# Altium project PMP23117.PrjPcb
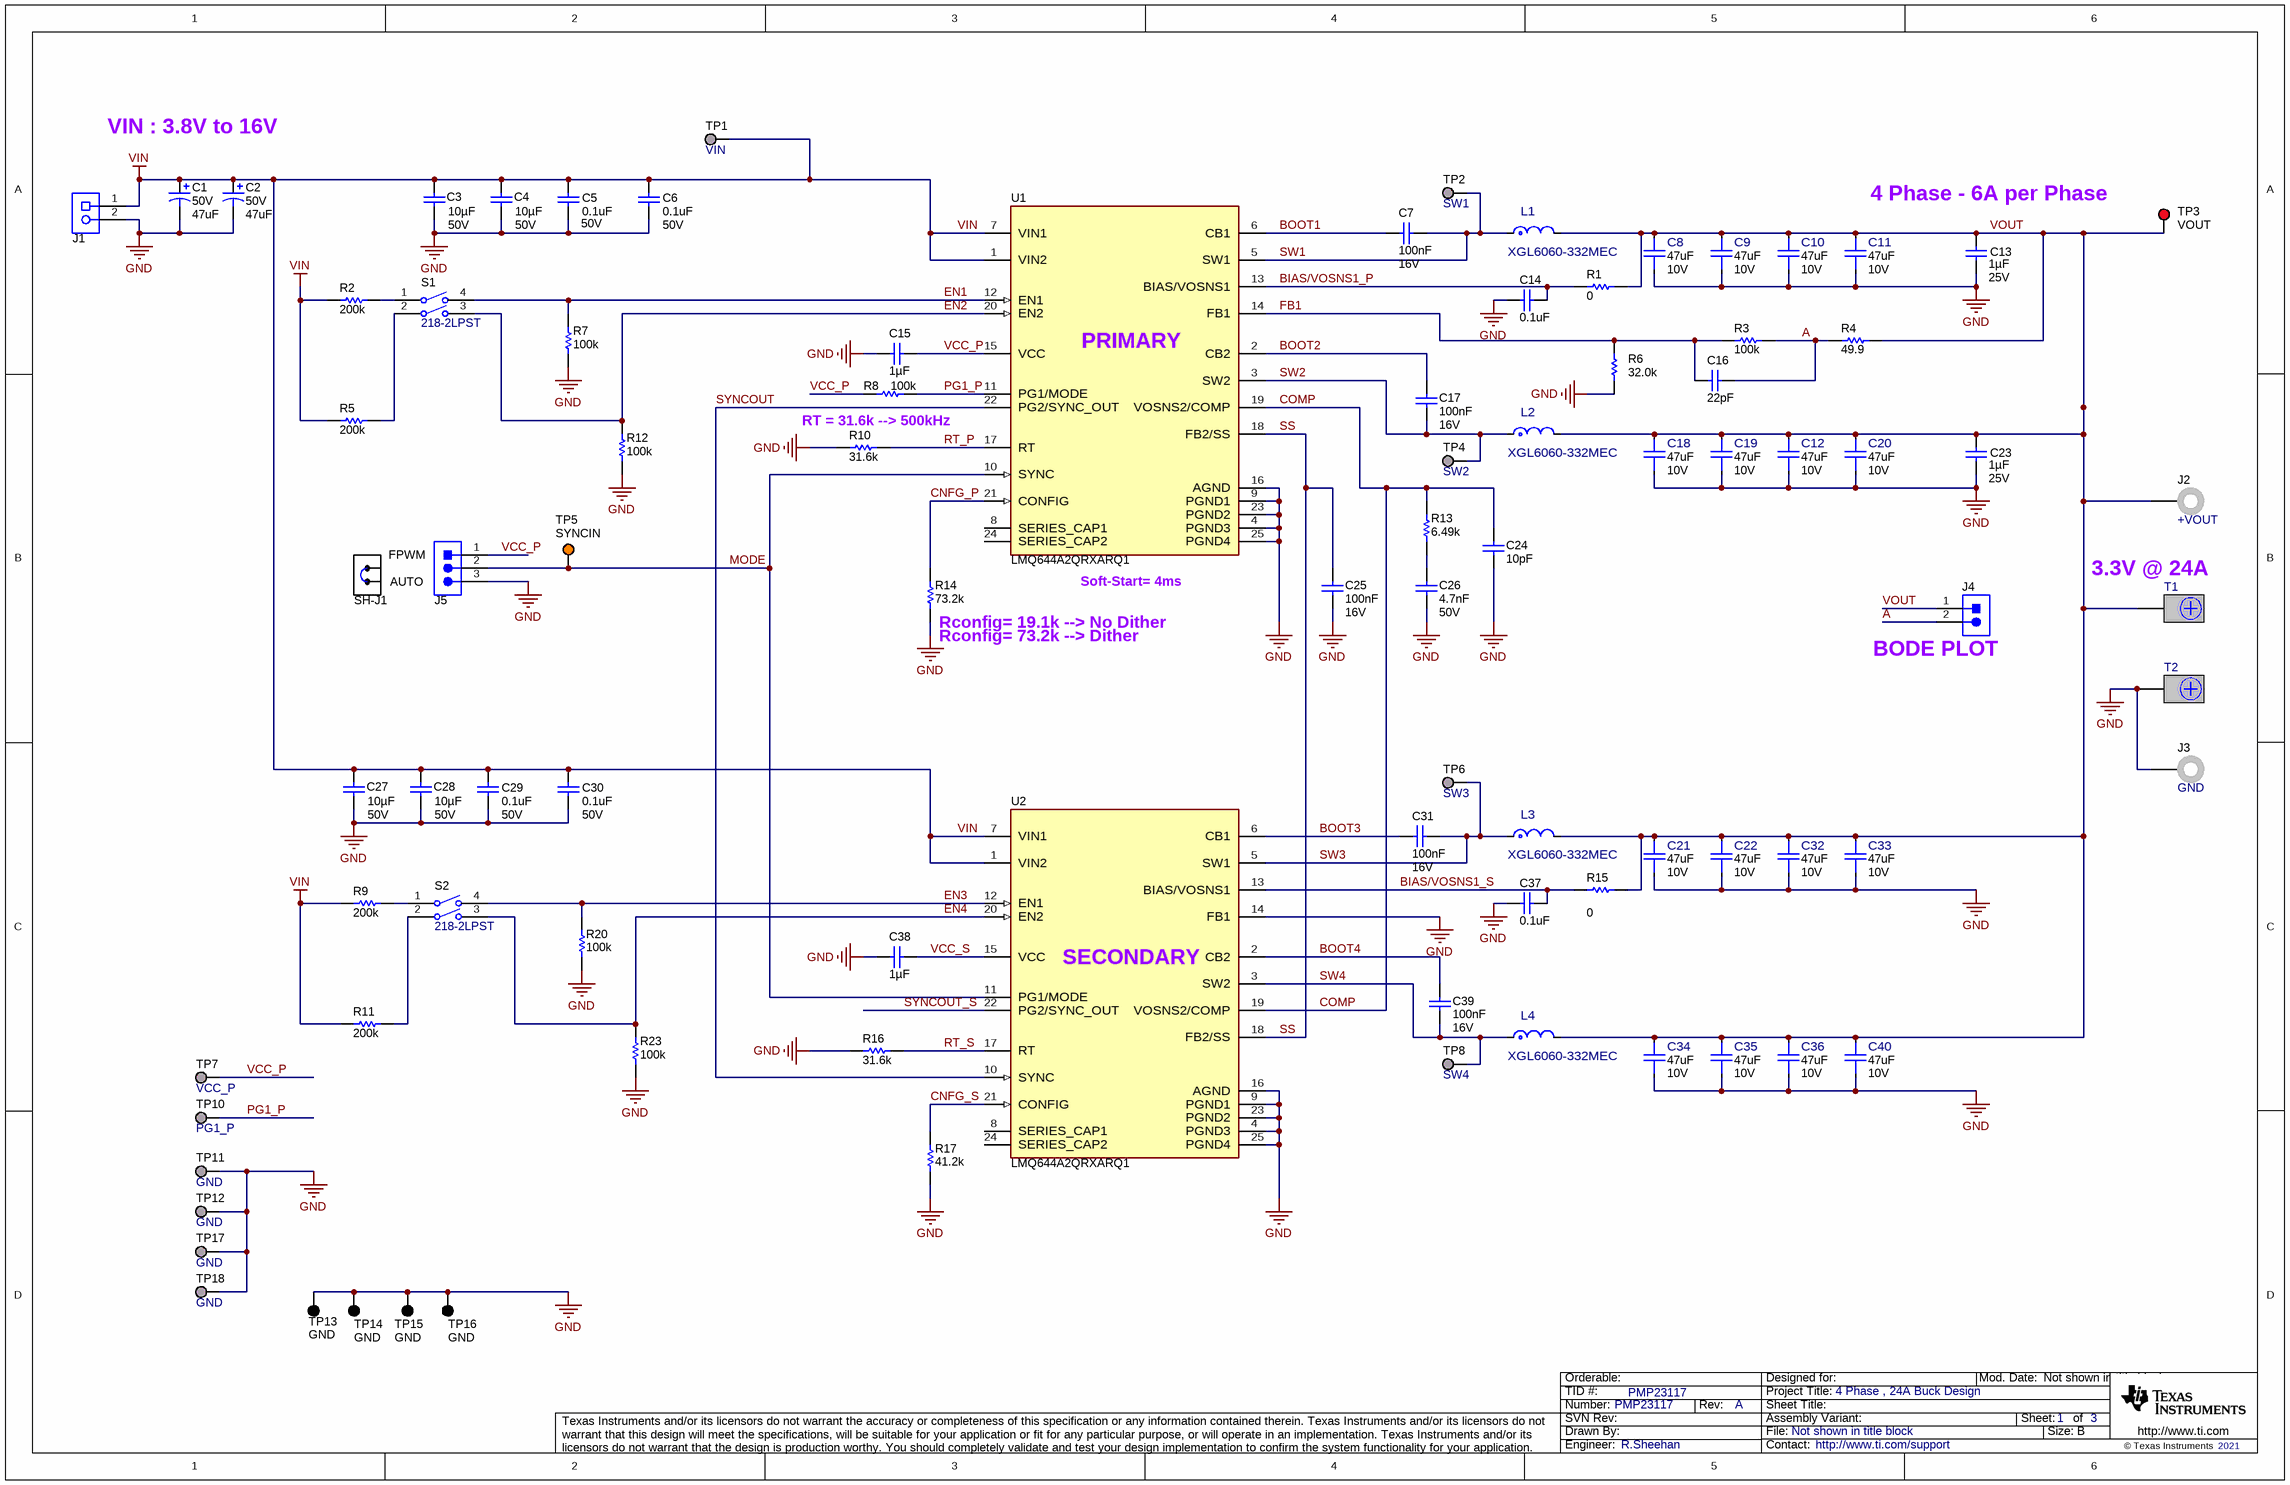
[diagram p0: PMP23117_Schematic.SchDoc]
CopyrightYear: 2021; PCB_Layout: R.Sheehan; PCB_Rev: A; PRJ_Engineer: R.Sheehan; PRJ_Number: PMP23117; PRJ_Title: 4 Phase , 24A Buck Design; SCH_Rev: A; TechSupport: http://www.ti.com/support; TID: PMP23117
3 sheets, 127 parts. Net scope: global (net labels, ports and power ports of the same name join across sheets).
Board file: PMP23117.PcbDoc
Sheets:
  PMP23117_Schematic.SchDoc
  PMP23117_EMI_Filter.SchDoc
  PMP23117_Hardware.SchDoc

## Sheet PMP23117_Schematic.SchDoc
size 431 x 279 mm; Date: Not shown in title block; ApprovedBy: Not shown in title block; CheckedBy: Not shown in title block; Author: Not shown in title block; CompanyName: Not shown in title block; Engineer: Not shown in title block; Organization: Not shown in title block; Address1: Not shown in title block; Address2: Not shown in title block; Address3: Not shown in title block; Address4: Not shown in title block; DocumentNumber: 1; Revision: Use project parameter SCH_Rev; SheetNumber: 1; SheetTotal: 3; PageSetup: Record=PageOptions¦CenterHorizontal=True¦CenterVertical=True¦PrintScale=1.00¦XCorrection=1.00¦YCorrection=1.00¦PrintKind=0¦BorderSize=5000000¦LeftOffset=0¦BottomOffset=0¦Orientation=2¦PaperLength=1000¦PaperWidth=1000¦Scale=100¦PaperSource=15¦PrintQuality=600¦MediaType=1¦DitherType=10¦PaperKind=Letter¦PrintScaleMode=1

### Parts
C1  VDC_V: 50V  ValueDisplayed: 47uF  [Panasonic_D]  (hidden comment: Cinblk)
C2  VDC_V: 50V  ValueDisplayed: 47uF  [Panasonic_D]  (hidden comment: Cinblk)
C3  ValueDisplayed: 10µF  VDC_V: 50V  [1206_190]  (hidden comment: CIN1_P)
C4  ValueDisplayed: 10µF  VDC_V: 50V  [1206_190]  (hidden comment: CIN2_P)
C5  VDC_V: 50V  ValueDisplayed: 0.1uF  [0402S]  (hidden comment: CHF2_P)
C6  VDC_V: 50V  ValueDisplayed: 0.1uF  [0402S]  (hidden comment: CHF1_P)
C7  Cap_F: 100nF  VDC_V: 16V  [0603L]  (hidden comment: GCM188R71C104KA37J)
C8  ValueDisplayed: 47uF  VDC_V: 10V  [FP-GRT32EC81A476KE13K_1210-MFG]  (hidden comment: GRT32EC81A476KE13K)
C9  ValueDisplayed: 47uF  VDC_V: 10V  [FP-GRT32EC81A476KE13K_1210-MFG]  (hidden comment: GRT32EC81A476KE13K)
C10  ValueDisplayed: 47uF  VDC_V: 10V  [FP-GRT32EC81A476KE13K_1210-MFG]  (hidden comment: GRT32EC81A476KE13K)
C11  ValueDisplayed: 47uF  VDC_V: 10V  [FP-GRT32EC81A476KE13K_1210-MFG]  (hidden comment: GRT32EC81A476KE13K)
C12  ValueDisplayed: 47uF  VDC_V: 10V  [FP-GRT32EC81A476KE13K_1210-MFG]  (hidden comment: GRT32EC81A476KE13K)
C13  Cap_F: 1µF  VDC_V: 25V  [0603L]  (hidden comment: Co11)
C14  ValueDisplayed: 0.1uF  [0603L]  (hidden comment: CBIAS_P)
C15  Cap_F: 1µF  [0603L]  (hidden comment: CVCC_P)
C16  ValueDisplayed: 22pF  [0603L]  (hidden comment: CFF)
C17  Cap_F: 100nF  VDC_V: 16V  [0603L]  (hidden comment: GCM188R71C104KA37J)
C18  ValueDisplayed: 47uF  VDC_V: 10V  [FP-GRT32EC81A476KE13K_1210-MFG]  (hidden comment: GRT32EC81A476KE13K)
C19  ValueDisplayed: 47uF  VDC_V: 10V  [FP-GRT32EC81A476KE13K_1210-MFG]  (hidden comment: GRT32EC81A476KE13K)
C20  ValueDisplayed: 47uF  VDC_V: 10V  [FP-GRT32EC81A476KE13K_1210-MFG]  (hidden comment: GRT32EC81A476KE13K)
C21  ValueDisplayed: 47uF  VDC_V: 10V  [FP-GRT32EC81A476KE13K_1210-MFG]  (hidden comment: GRT32EC81A476KE13K)
C22  ValueDisplayed: 47uF  VDC_V: 10V  [FP-GRT32EC81A476KE13K_1210-MFG]  (hidden comment: GRT32EC81A476KE13K)
C23  Cap_F: 1µF  VDC_V: 25V  [0603L]  (hidden comment: Co12)
C24  ValueDisplayed: 10pF  [0603L]  (hidden comment: CHFP)
C25  Cap_F: 100nF  VDC_V: 16V  [0603L]  (hidden comment: GCM188R71C104KA37J)
C26  Cap_F: 4.7nF  VDC_V: 50V  [0603L]  (hidden comment: GCM188R71H472KA37D)
C27  ValueDisplayed: 10µF  VDC_V: 50V  [1206_190]  (hidden comment: CIN1_S)
C28  ValueDisplayed: 10µF  VDC_V: 50V  [1206_190]  (hidden comment: CIN2_S)
C29  VDC_V: 50V  ValueDisplayed: 0.1uF  [0402S]  (hidden comment: CHF2_S)
C30  VDC_V: 50V  ValueDisplayed: 0.1uF  [0402S]  (hidden comment: CHF1_S)
C31  Cap_F: 100nF  VDC_V: 16V  [0603L]  (hidden comment: GCM188R71C104KA37J)
C32  ValueDisplayed: 47uF  VDC_V: 10V  [FP-GRT32EC81A476KE13K_1210-MFG]  (hidden comment: GRT32EC81A476KE13K)
C33  ValueDisplayed: 47uF  VDC_V: 10V  [FP-GRT32EC81A476KE13K_1210-MFG]  (hidden comment: GRT32EC81A476KE13K)
C34  ValueDisplayed: 47uF  VDC_V: 10V  [FP-GRT32EC81A476KE13K_1210-MFG]  (hidden comment: GRT32EC81A476KE13K)
C35  ValueDisplayed: 47uF  VDC_V: 10V  [FP-GRT32EC81A476KE13K_1210-MFG]  (hidden comment: GRT32EC81A476KE13K)
C36  ValueDisplayed: 47uF  VDC_V: 10V  [FP-GRT32EC81A476KE13K_1210-MFG]  (hidden comment: GRT32EC81A476KE13K)
C37  ValueDisplayed: 0.1uF  [0603L]  (hidden comment: CBIAS_S)
C38  Cap_F: 1µF  [0603L]  (hidden comment: CVCC_S)
C39  Cap_F: 100nF  VDC_V: 16V  [0603L]  (hidden comment: GCM188R71C104KA37J)
C40  ValueDisplayed: 47uF  VDC_V: 10V  [FP-GRT32EC81A476KE13K_1210-MFG]  (hidden comment: GRT32EC81A476KE13K)
J1  VIN  [Wurth_691101710002]  (value not drawn)
J2  +VOUT  [Johnson_108-0740-001]
J3  GND  [Johnson_108-0740-001]
J4  BODE  [TSW-102-07-G-S]  (value not drawn)
J5  MODE  [PBC03SAAN]  (value not drawn)
L1  XGL6060-332MEC  [FP-XGL6060-332MEC_SMT_6MM51_6MM71-MFG]
L2  XGL6060-332MEC  [FP-XGL6060-332MEC_SMT_6MM51_6MM71-MFG]
L3  XGL6060-332MEC  [FP-XGL6060-332MEC_SMT_6MM51_6MM71-MFG]
L4  XGL6060-332MEC  [FP-XGL6060-332MEC_SMT_6MM51_6MM71-MFG]
R1  ValueDisplayed: 0  [0402L]  (hidden comment: RSNS1_P)
R2  ValueDisplayed: 200k  [0603L]  (hidden comment: CRCW0603200KFKEA)
R3  ValueDisplayed: 100k  [0603L]  (hidden comment: RFBT)
R4  ValueDisplayed: 49.9  [0805L]  (hidden comment: RINJ)
R5  ValueDisplayed: 200k  [0603L]  (hidden comment: CRCW0603200KFKEA)
R6  ValueDisplayed: 32.0k  [0603L]  (hidden comment: RFBB)
R7  ValueDisplayed: 100k  [0603L]  (hidden comment: CRCW0603100KFKEA)
R8  ValueDisplayed: 100k  [0603L]  (hidden comment: RPG1_P)
R9  ValueDisplayed: 200k  [0603L]  (hidden comment: CRCW0603200KFKEA)
R10  ValueDisplayed: 31.6k  [0603L]  (hidden comment: CRCW060331K6FKEA)
R11  ValueDisplayed: 200k  [0603L]  (hidden comment: CRCW0603200KFKEA)
R12  ValueDisplayed: 100k  [0603L]  (hidden comment: CRCW0603100KFKEA)
R13  ValueDisplayed: 6.49k  [0603L]  (hidden comment: CRCW06036K49FKEA)
R14  ValueDisplayed: 73.2k  [0603L]  (hidden comment: CRCW060373K2FKEA)
R15  ValueDisplayed: 0  [0402L]  (hidden comment: RSNS1_S)
R16  ValueDisplayed: 31.6k  [0603L]  (hidden comment: CRCW060331K6FKEA)
R17  ValueDisplayed: 41.2k  [0603L]  (hidden comment: CRCW060341K2FKEA)
R20  ValueDisplayed: 100k  [0603L]  (hidden comment: CRCW0603100KFKEA)
R23  ValueDisplayed: 100k  [0603L]  (hidden comment: CRCW0603100KFKEA)
S1  218-2LPST  [SW_218-2LP]
S2  218-2LPST  [SW_218-2LP]
SH-J1  SNT-100-BK-G  [SNT-100-BK-G]  (value not drawn)
T1  VOUT  [Panduit_CXS70-14-C]  (value not drawn)
T2  GND  [Panduit_CXS70-14-C]  (value not drawn)
TP1  VIN  [Harwin_S2751-46R]  (mechanical)
TP2  SW1  [Harwin_S2751-46R]  (mechanical)
TP3  VOUT  [Keystone5010]
TP4  SW2  [Harwin_S2751-46R]  (mechanical)
TP5  SYNCIN  [Keystone5013]
TP6  SW3  [Harwin_S2751-46R]  (mechanical)
TP7  VCC_P  [Harwin_S2751-46R]  (mechanical)
TP8  SW4  [Harwin_S2751-46R]  (mechanical)
TP10  PG1_P  [Harwin_S2751-46R]  (mechanical)
TP11  GND  [Harwin_S2751-46R]  (mechanical)
TP12  GND  [Harwin_S2751-46R]  (mechanical)
TP13  GND  [Keystone5011]
TP14  GND  [Keystone5011]
TP15  GND  [Keystone5011]
TP16  GND  [Keystone5011]
TP17  GND  [Harwin_S2751-46R]  (mechanical)
TP18  GND  [Harwin_S2751-46R]  (mechanical)
U1  LMQ644A2QRXARQ1  [RXA0024A-MFG]
U2  LMQ644A2QRXARQ1  [RXA0024A-MFG]

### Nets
GND: C1.2(-) C2.2(-) C3.1 C4.1 C5.2 C6.2 C8.1 C9.1 C10.1 C11.1 C12.1 C13.2 C14.1 C15.1 C18.1 C19.1 C20.1 C21.1 C22.1 C23.2 C24.1 C25.1 C26.2 C27.1 C28.1 C29.2 C30.2 C32.1 C33.1 C34.1 C35.1 C36.1 C37.1 C38.1 C40.1 J1.2 J3.1 J5.3 R6.1 R7.1 R10.1 R12.1 R14.1 R16.1 R17.1 R20.1 R23.1 T2.1 TP11.1 TP12.1 TP13.1 TP14.1 TP15.1 TP16.1 TP17.1 TP18.1 U1.4(PGND3) U1.9(PGND1) U1.16(AGND) U1.23(PGND2) U1.25(PGND4) U2.4(PGND3) U2.9(PGND1) U2.14(FB1) U2.16(AGND) U2.23(PGND2) U2.25(PGND4)
VIN: C1.1(+) C2.1(+) C3.2 C4.2 C5.1 C6.1 C27.2 C28.2 C29.1 C30.1 J1.1 R2.1 R5.1 R9.1 R11.1 TP1.1 U1.1(VIN2) U1.7(VIN1) U2.1(VIN2) U2.7(VIN1)
A: C16.1 J4.2 R3.1 R4.1
BIAS/VOSNS1_P: C14.2 R1.1 U1.13(BIAS/VOSNS1)
BIAS/VOSNS1_S: C37.2 R15.2 U2.13(BIAS/VOSNS1)
BOOT1: C7.1 U1.6(CB1)
BOOT2: C17.2 U1.2(CB2)
BOOT3: C31.2 U2.6(CB1)
BOOT4: C39.1 U2.2(CB2)
CNFG_P: R14.2 U1.21(CONFIG)
CNFG_S: R17.2 U2.21(CONFIG)
COMP: C24.2 R13.2 U1.19(VOSNS2/COMP) U2.19(VOSNS2/COMP)
EN1: R7.2 S1.4 U1.12(EN1)
EN2: R12.2 S1.3 U1.20(EN2)
EN3: R20.2 S2.4 U2.12(EN1)
EN4: R23.2 S2.3 U2.20(EN2)
FB1: C16.2 R3.2 R6.2 U1.14(FB1)
MODE: J5.2 TP5.1 U1.10(SYNC) U2.11(PG1/MODE)
PG1_P: R8.2 TP10.1 U1.11(PG1/MODE)
RT_P: R10.2 U1.17(RT)
RT_S: R16.2 U2.17(RT)
SS: C25.2 U1.18(FB2/SS) U2.18(FB2/SS)
SW1: C7.2 L1.1 TP2.1 U1.5(SW1)
SW2: C17.1 L2.1 TP4.1 U1.3(SW2)
SW3: C31.1 L3.1 TP6.1 U2.5(SW1)
SW4: C39.2 L4.1 TP8.1 U2.3(SW2)
SYNCOUT: U1.22(PG2/SYNC_OUT) U2.10(SYNC)
SYNCOUT_S: U2.22(PG2/SYNC_OUT)
VCC_P: C15.2 J5.1 R8.1 TP7.1 U1.15(VCC)
VCC_S: C38.2 U2.15(VCC)
VOUT: C8.2 C9.2 C10.2 C11.2 C12.2 C13.1 C18.2 C19.2 C20.2 C21.2 C22.2 C23.1 C32.2 C33.2 C34.2 C35.2 C36.2 C40.2 J2.1 J4.1 L1.2 L2.2 L3.2 L4.2 R1.2 R4.2 R15.1 T1.1 TP3.1
NetC26_1: C26.1 R13.1
NetR2_2: R2.2 S1.1
NetR5_2: R5.2 S1.2
NetR9_2: R9.2 S2.1
NetR11_2: R11.2 S2.2

Not connected (* = marked no-connect by the designer): U1 8(SERIES_CAP1) 24(SERIES_CAP2); U2 8(SERIES_CAP1) 24(SERIES_CAP2)

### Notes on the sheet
- VIN : 3.8V to 16V
- 4 Phase - 6A per Phase
- (near U1) PRIMARY
- RT = 31.6k --> 500kHz
- FPWM
- (near T1) 3.3V @ 24A
- AUTO
- (near R14) Rconfig= 73.2k --> Dither
- (near R14) Rconfig= 19.1k --> No Dither
- (near U1) Soft-Start= 4ms
- (near J4) BODE PLOT
- (near U2) SECONDARY

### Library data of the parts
C1 C2 = CMP-0011204-2: CAP, AL, 47 uF, 50 V, +/- 20%, 0.68 ohm, AEC-Q200 Grade 2, SMD; Manufacturer: Panasonic; PartNumber: EEEFT1H470AP; TaMin_C: -55°C; ESR_ohm: 6.8d; Polarized: Y; SizeAreaWB_mm2: 73.96; U/M: EA; Value: 47uF; TaMax_C: 105°C; SizeZ_mm: 6.1; SizeX_mm: 6.6; Cap_Case: 6.3x5.8mm; SizeArea_mm2: 43.56; CompType: Capacitor; Cap_F: 47µF; IRMS_A: 1.95dA; AEC Grade: 2; AEC Category: Q200
C3 C4 C27 C28 = CMP-0085950-1: CAP, CERM, 10 µF, 50 V,+/- 10%, X7R, AEC-Q200 Grade 1, 1206; Manufacturer: TDK; PartNumber: CGA5L1X7R1H106K160AC; SizeZ_mm: 1.9; Value: 10uF; Cap_Case: 1206; AEC Grade: 1; TaMin_C: -55°C; U/M: EA; CompType: Capacitor; SizeArea_mm2: 5.12; TaMax_C: 125°C; AEC Qualified: Y; AEC Category: Q200; SizeX_mm: 3.2; SizeY_mm: 1.6; Polarized: N; SizeAreaWB_mm2: 10.92
C5 C6 C29 C30 = CMP-0006356-2: CAP, CERM, 0.1 uF, 50 V, +/- 10%, X7R, AEC-Q200 Grade 1, 0402; Manufacturer: MuRata; PartNumber: GCM155R71H104KE02D; TaMin_C: -55°C; Polarized: N; SizeAreaWB_mm2: 3; Value1: Unknown; U/M: EA; Value: 0.1uF; TaMax_C: 125°C; SizeZ_mm: 0.6; SizeX_mm: 1; SizeY_mm: 0.5; Cap_Case: 0402; AEC Qualified: Y; Cap_F: 100nF; AEC Category: Q200
C7 C17 C25 C31 C39 = CMP-0007135-4: CAP, CERM, 0.1 uF, 16 V, +/- 10%, X7R, AEC-Q200 Grade 1, 0603; Manufacturer: MuRata; TaMin_C: -55°C; Polarized: N; SizeAreaWB_mm2: 4.68; Value1: Unknown; U/M: EA; Value: 0.1uF; TaMax_C: 125°C; SizeZ_mm: 1; SizeX_mm: 1.6; SizeY_mm: 0.8; Cap_Case: 0603; SizeArea_mm2: 1.28; AEC Qualified: Y; AEC Category: Q200
C8-C12 C18-C22 C32-C36 C40 = CMP-0093224-1: Multi-Layer Ceramic Capacitor 47uF 10VDC X6S 10% 1210 Emboss T/R; Manufacturer: Murata; SizeZ_mm: 2.7mm; TempCo: 22%; Value: 47µF; AEC Qualified: Yes; AEC Grade: Grade 1
C13 C23 = CMP-0007139-4: CAP, CERM, 1 uF, 25 V, +/- 10%, X7R, AEC-Q200 Grade 1, 0603; Manufacturer: MuRata; PartNumber: GCM188R71E105KA64D; TaMin_C: -55°C; Polarized: N; SizeAreaWB_mm2: 4.68; Value1: Unknown; U/M: EA; Value: 1uF; TaMax_C: 125°C; SizeZ_mm: 1; SizeX_mm: 1.6; SizeY_mm: 0.8; Cap_Case: 0603; SizeArea_mm2: 1.28; CompType: Capacitor; AEC Qualified: Y; AEC Category: Q200
C14 C37 = CMP-0007010-5: CAP, CERM, 0.1 uF, 50 V, +/- 10%, X5R, 0603; Manufacturer: TDK; PartNumber: C1608X5R1H104K080AA; TaMin_C: -55°C; ESR_ohm: 0.0296; Polarized: N; SizeAreaWB_mm2: 4.68; Value1: 0.0296 ohm; U/M: EA; Value: 0.1uF; TaMax_C: 85°C; SizeZ_mm: 1; SizeX_mm: 1.6; SizeY_mm: 0.8; Cap_Case: 0603; Value2: 50V; SizeArea_mm2: 1.28; Cap_F: 100nF; IRMS_A: 971.99mA; AEC Category: Q200
C15 C38 = CMP-0007137-5: CAP, CERM, 1 uF, 16 V, +/- 20%, X7R, AEC-Q200 Grade 1, 0603; Manufacturer: MuRata; PartNumber: GCM188R71C105MA64D; TaMin_C: -55°C; Polarized: N; SizeAreaWB_mm2: 4.68; Value1: Unknown; U/M: EA; Value: 1uF; TaMax_C: 125°C; SizeZ_mm: 1; SizeX_mm: 1.6; SizeY_mm: 0.8; Cap_Case: 0603; Value2: 16V; SizeArea_mm2: 1.28; CompType: Capacitor; AEC Qualified: Y; AEC Category: Q200
C16 = CMP-0006775-4: CAP, CERM, 22 pF, 50 V, +/- 5%, C0G/NP0, 0603; Manufacturer: AVX; PartNumber: 06035A220JAT2A; TaMin_C: -55°C; ESR_ohm: 0.259; Polarized: N; SizeAreaWB_mm2: 4.68; Value1: 0.259 ohm; U/M: EA; Value: 22pF; TaMax_C: 125°C; SizeZ_mm: 1; SizeX_mm: 1.6; SizeY_mm: 0.8; Cap_Case: 0603; Value2: 50V; SizeArea_mm2: 1.28; CompType: Capacitor; AEC Category: Q200
C24 = CMP-0007236-4: CAP, CERM, 10 pF, 100 V, +/- 5%, C0G/NP0, 0603; Manufacturer: MuRata; PartNumber: GRM1885C2A100JA01D; TaMin_C: -55°C; Polarized: N; SizeAreaWB_mm2: 4.68; Value1: Unknown; U/M: EA; Value: 10pF; TaMax_C: 125°C; SizeZ_mm: 1; SizeX_mm: 1.6; SizeY_mm: 0.8; Cap_Case: 0603; Value2: 100V; SizeArea_mm2: 1.28; CompType: Capacitor; AEC Category: Q200
C26 = CMP-0007146-4: CAP, CERM, 4700 pF, 50 V, +/- 10%, X7R, AEC-Q200 Grade 1, 0603; Manufacturer: MuRata; TaMin_C: -55°C; Polarized: N; SizeAreaWB_mm2: 4.68; Value1: Unknown; U/M: EA; Value: 4700pF; TaMax_C: 125°C; SizeZ_mm: 1; SizeX_mm: 1.6; SizeY_mm: 0.8; Cap_Case: 0603; SizeArea_mm2: 1.28; AEC Qualified: Y; AEC Category: Q200
J1 = CMP-0054828-1: Terminal Block, 5 mm, 2x1, Tin, TH; Manufacturer: Wurth Elektronik; PartNumber: 691 101 710 002; CNHeader: FALSE; Green_Lifecycle: Active; Green_REACh: Passed; CT: TRUE
J2 J3 = CMP-0055387-2: Standard Banana Jack, Uninsulated, 15A; Manufacturer: Cinch Connectivity; CNHeader: FALSE; CT: TRUE; Green_Lifecycle: Active; Green_REACh: Passed
J4 = CMP-0075405-3: Header, 100mil, 2x1, Gold, TH; Manufacturer: Samtec; Pitch_mm: 2.54; Cert_VDE: N; Gender: Male; Cert_CSA: Y; Voltage_V: 550V; Green_REACh: Passed; Current_A: 6.3A; Green_Lifecycle: Active; Row_Count: 1
J5 = CMP-0002334-1: Header, 100mil, 3x1, Gold, TH; Manufacturer: Sullins Connector Solutions; CNHeader: TRUE; CT: FALSE; Green_Lifecycle: Not Set; Green_REACh: Incomplete
L1-L4 = CMP-0093175-1: Shielded Power Inductors 3.3uH 20% tol, 6.5mOhm 16.6A; Manufacturer: Coilcraft; Shrouded: true; AEC Grade: Grade 1; TaMin_C: -40°C; Ind_H: 3.3µH; Test Frequency: 1MHz; DCR_ohm: 6.5m; Isat: 6.6A; Material: Composite; Self Resonant Frequency: 24MHz; SizeZ_mm: 6.1mm; AEC Qualified: Yes; TaMax_C: +125°C
R1 R15 = CMP-0081856-1: RES, 0, 0%, 0.2 W, AEC-Q200 Grade 0, 0402; PartNumber: CRCW04020000Z0EDHP; Manufacturer: Vishay-Dale; SizeAreaWB_mm2: 3; SizeArea_mm2: 0.5; AEC Qualified: Y; AEC Category: Q200; Value: 0; SizeZ_mm: 0.6; Power_W: 200mW; VDC_V: 50V; Value2: 0.2W; CompType: Resistor; SizeX_mm: 1
R2 R5 R9 R11 = CMP-0022200-4: RES, 200 k, 1%, 0.1 W, AEC-Q200 Grade 0, 0603; Manufacturer: Vishay-Dale; Power_W: 100mW; TempCo: 100 ppm/C; Value: 200k; EIA_Code: E96; SizeX_mm: 1.6; SizeY_mm: 0.8; SizeZ_mm: 1; Value2: 0.1W; SizeArea_mm2: 1.28; AEC Qualified: Y; VDC_V: 75V; AEC Category: Q200; AEC Grade: 0
R3 = CMP-0025685-3: RES, 100 k, 0.1%, 0.1 W, AEC-Q200 Grade 1, 0603; Manufacturer: Vishay-Dale; PartNumber: TNPW0603100KBEEA; Power_W: 100mW; TempCo: 25 ppm/C; U/M: EA; Value: 100k; EIA_Code: E192; SizeX_mm: 1.6; SizeY_mm: 0.8; SizeZ_mm: 1; Value2: 0.1W; SizeArea_mm2: 1.28; CompType: Resistor; AEC Qualified: Y; VDC_V: 75V; AEC Category: Q200
R4 = CMP-0021284-3: RES, 49.9, 1%, 0.125 W, AEC-Q200 Grade 0, 0805; Manufacturer: Vishay-Dale; PartNumber: CRCW080549R9FKEA; Power_W: 125mW; TempCo: 100 ppm/C; Value_Code: 49R9; Value: 49.9; EIA_Code: E96; SizeX_mm: 2; SizeY_mm: 1.25; SizeZ_mm: 1.45; Value2: 0.125W; SizeArea_mm2: 2.5; CompType: Resistor; AEC Qualified: Y; VDC_V: 150V; AEC Category: Q200; AEC Grade: 0
R6 = CMP-0024118-3: RES, 32.0 k, 0.1%, 0.1 W, 0603; Manufacturer: Yageo America; PartNumber: RT0603BRD0732KL; Power_W: 100mW; TempCo: 25 ppm/C; Value_Code: 32k0; U/M: EA; Value: 32.0k; EIA_Code: E192; Res_ohm: 32k; SizeX_mm: 1.6; SizeY_mm: 0.8; SizeZ_mm: 1; Value2: 0.1W; SizeArea_mm2: 1.28; CompType: Resistor; VDC_V: 75V; AEC Category: Q200
R7 R12 R20 R23 = CMP-0021990-4: RES, 100 k, 1%, 0.1 W, AEC-Q200 Grade 0, 0603; Manufacturer: Vishay-Dale; Power_W: 100mW; TempCo: 100 ppm/C; Value: 100k; EIA_Code: E96; SizeX_mm: 1.6; SizeY_mm: 0.8; SizeZ_mm: 1; Value2: 0.1W; SizeArea_mm2: 1.28; AEC Qualified: Y; VDC_V: 75V; AEC Category: Q200; AEC Grade: 0
R8 = CMP-0022735-5: RES, 100 k, 1%, 0.1 W, 0603; Manufacturer: Yageo; PartNumber: RC0603FR-07100KL; Power_W: 100mW; TempCo: 100 ppm/C; Value: 100k; EIA_Code: E96; SizeX_mm: 1.6; SizeY_mm: 0.8; SizeZ_mm: 1; Value2: 0.1W; SizeArea_mm2: 1.28; CompType: Resistor; AEC Qualified: N; VDC_V: 75V; AEC Category: Q200; SizeAreaWB_mm2: 4.68
R10 R16 = CMP-0022330-4: RES, 31.6 k, 1%, 0.1 W, AEC-Q200 Grade 0, 0603; Manufacturer: Vishay-Dale; Power_W: 100mW; TempCo: 100 ppm/C; Value_Code: 31k6; Value: 31.6k; EIA_Code: E96; SizeX_mm: 1.6; SizeY_mm: 0.8; SizeZ_mm: 1; Value2: 0.1W; SizeArea_mm2: 1.28; AEC Qualified: Y; VDC_V: 75V; AEC Category: Q200; AEC Grade: 0
R13 = CMP-0022561-4: RES, 6.49 k, 1%, 0.1 W, AEC-Q200 Grade 0, 0603; Manufacturer: Vishay-Dale; Power_W: 100mW; TempCo: 100 ppm/C; Value_Code: 6k49; Value: 6.49k; EIA_Code: E96; SizeX_mm: 1.6; SizeY_mm: 0.8; SizeZ_mm: 1; Value2: 0.1W; SizeArea_mm2: 1.28; AEC Qualified: Y; VDC_V: 75V; AEC Category: Q200; AEC Grade: 0
R14 = CMP-0022585-4: RES, 73.2 k, 1%, 0.1 W, AEC-Q200 Grade 0, 0603; Manufacturer: Vishay-Dale; Power_W: 100mW; TempCo: 100 ppm/C; Value_Code: 73k2; Value: 73.2k; EIA_Code: E96; SizeX_mm: 1.6; SizeY_mm: 0.8; SizeZ_mm: 1; Value2: 0.1W; SizeArea_mm2: 1.28; AEC Qualified: Y; VDC_V: 75V; AEC Category: Q200; AEC Grade: 0
R17 = CMP-0022414-4: RES, 41.2 k, 1%, 0.1 W, AEC-Q200 Grade 0, 0603; Manufacturer: Vishay-Dale; Power_W: 100mW; TempCo: 100 ppm/C; Value_Code: 41k2; Value: 41.2k; EIA_Code: E96; SizeX_mm: 1.6; SizeY_mm: 0.8; SizeZ_mm: 1; Value2: 0.1W; SizeArea_mm2: 1.28; AEC Qualified: Y; VDC_V: 75V; AEC Category: Q200; AEC Grade: 0
S1 S2 = CMP-0002230-1: Switch, SPST, 2 Pos, 25mA, 24VDC, SMD; Manufacturer: CTS Electrocomponents; CurrentRating_mA: 25A; PositionCount: 2; VDC_V: 24V; SwitchFunction: Off-On
SH-J1 = CMP-0003623-3: Shunt, 100mil, Gold plated, Black; Alternate PartNumber: 969102-0000-DA; Manufacturer: Samtec; Alternate Manufacturer: 3M; Value: 1x2
T1 T2 = CMP-0075010-1: Terminal 70A Lug; Manufacturer: Panduit; PartNumber: CXS70-14-C; CNHeader: False; Green_Lifecycle: Not Set; Green_REACh: Incomplete; CompType: Screw Terminal
TP1 TP2 TP4 TP6-TP8 TP10-TP12 TP17 TP18 = CMP-0003968-1: Test Point, SMT; Manufacturer: Harwin; Key: S2751-46R
TP3 = CMP-0055147-1: Test Point, Multipurpose, Red, TH; Manufacturer: Keystone; PartNumber: 5010; CNHeader: FALSE; Green_Lifecycle: Active; Green_REACh: Passed; ContactFinish: Silver; CT: TRUE
TP5 = CMP-0055150-1: Test Point, Multipurpose, Orange, TH; Manufacturer: Keystone; PartNumber: 5013; CNHeader: FALSE; Green_Lifecycle: Active; Green_REACh: Passed; ContactFinish: Silver; CT: TRUE
TP13-TP16 = CMP-0055148-1: Test Point, Multipurpose, Black, TH; Manufacturer: Keystone; PartNumber: 5011; CNHeader: FALSE; Green_Lifecycle: Active; Green_REACh: Passed; ContactFinish: Silver; CT: TRUE
U1 U2 = CMP-0091557-1: LMQ644A2-Q1 3-V to 36-V, 12A, Low Iq dual buck converter; Manufacturer: Texas Instruments; Min Supply Voltage: 3V; Max Duty Cycle: 99%; TaMin_C: -40°C; Output Voltage: 0.8-20V; AEC Grade: Grade 1; Output Type: Fixed,AdjustableProgrammable; TaMax_C: +125°C; AEC Qualified: Yes; SizeZ_mm: 0.7mm; TJmax_C: +150°C; Max Supply Voltage: 36V; Switching Frequency: 0.1-2.2MHz; Number Of Outputs: 2; Standoff Height: 0mm; Nominal Supply Current: 9-25uA

## Sheet PMP23117_EMI_Filter.SchDoc
size 431 x 279 mm; Date: Not shown in title block; ApprovedBy: Not shown in title block; CheckedBy: Not shown in title block; Author: Not shown in title block; CompanyName: Not shown in title block; Engineer: Not shown in title block; Organization: Not shown in title block; Address1: Not shown in title block; Address2: Not shown in title block; Address3: Not shown in title block; Address4: Not shown in title block; DocumentNumber: 2; Revision: Use project parameter SCH_Rev; SheetNumber: 2; SheetTotal: 3; PageSetup: Record=PageOptions¦CenterHorizontal=True¦CenterVertical=True¦PrintScale=1.00¦XCorrection=1.00¦YCorrection=1.00¦PrintKind=0¦BorderSize=5000000¦LeftOffset=0¦BottomOffset=0¦Orientation=2¦PaperLength=1000¦PaperWidth=1000¦Scale=100¦PaperSource=15¦PrintQuality=600¦MediaType=1¦DitherType=10¦PaperKind=Letter¦PrintScaleMode=1
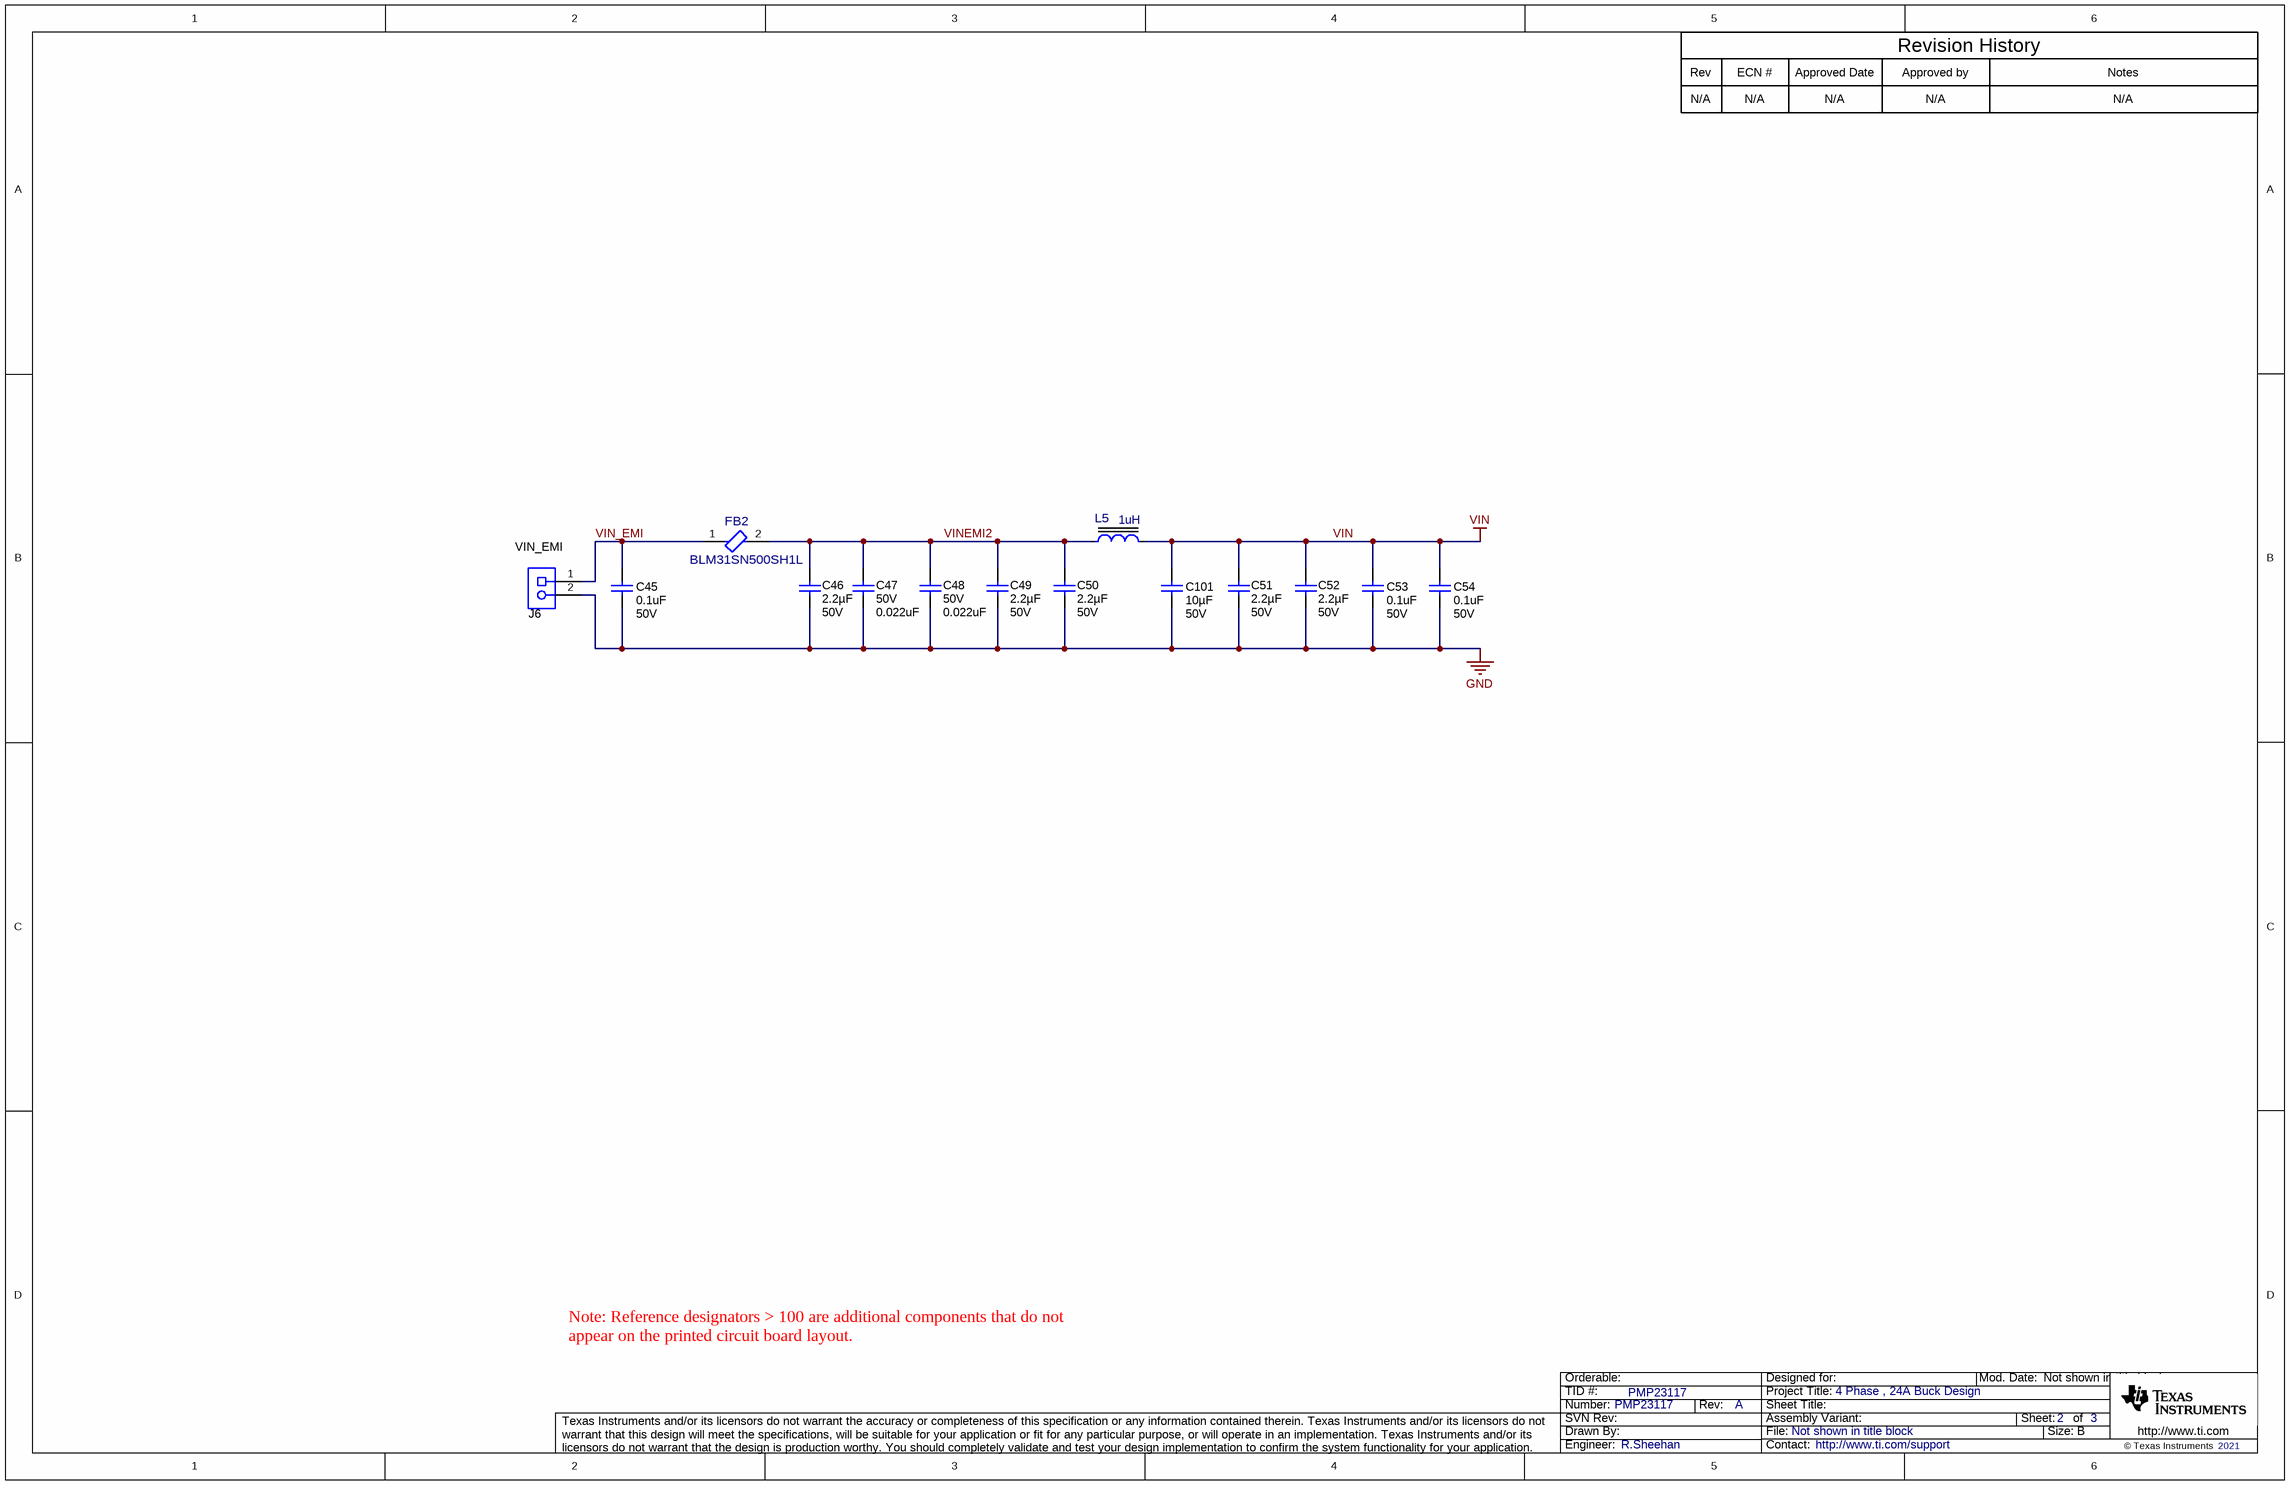
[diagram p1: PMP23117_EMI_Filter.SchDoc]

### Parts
C45  VDC_V: 50V  ValueDisplayed: 0.1uF  [0402L]  (hidden comment: CFLTIN)
C46  Cap_F: 2.2µF  VDC_V: 50V  [0805L]  (hidden comment: CFLT7)
C47  VDC_V: 50V  ValueDisplayed: 0.022uF  [0402L]  (hidden comment: CFLT6)
C48  VDC_V: 50V  ValueDisplayed: 0.022uF  [0402L]  (hidden comment: CFLT5)
C49  Cap_F: 2.2µF  VDC_V: 50V  [0805L]  (hidden comment: CFLT4)
C50  Cap_F: 2.2µF  VDC_V: 50V  [0805L]  (hidden comment: CFLT3)
C51  Cap_F: 2.2µF  VDC_V: 50V  [0805L]  (hidden comment: CFLT2)
C52  Cap_F: 2.2µF  VDC_V: 50V  [0805L]  (hidden comment: CFLT1)
C53  VDC_V: 50V  ValueDisplayed: 0.1uF  [0402L]  (hidden comment: CFLTHF2)
C54  VDC_V: 50V  ValueDisplayed: 0.1uF  [0402L]  (hidden comment: CFLTHF1)
C101  ValueDisplayed: 10µF  VDC_V: 50V  [1206_190]  (hidden comment: CIN2_P)
FB2  BLM31SN500SH1L  [FP-BLM31SN500SH1L_1206-MFG]
J6  VIN_EMI  [Wurth_691101710002]
L5  ValueDisplayed: 1uH  [FP-XEL5030-102MEB_SMT_5MM28_5MM48-MFG]  (hidden comment: LFLT)

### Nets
GND: C45.2 C46.2 C47.2 C48.2 C49.2 C50.2 C51.2 C52.2 C53.2 C54.2 C101.1 J6.2
VIN: C51.1 C52.1 C53.1 C54.1 C101.2 L5.2
VIN_EMI: C45.1 FB2.1 J6.1
VINEMI2: C46.1 C47.1 C48.1 C49.1 C50.1 FB2.2 L5.1

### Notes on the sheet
- Rev
- N/A
- ECN #
- Approved Date
- Approved by
- Revision History
- Notes
- Note: Reference designators > 100 are additional components that do not appear on the printed circuit board layout.

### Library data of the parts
C45 C53 C54 = CMP-0006356-2: CAP, CERM, 0.1 uF, 50 V, +/- 10%, X7R, AEC-Q200 Grade 1, 0402; Manufacturer: MuRata; PartNumber: GCM155R71H104KE02D; TaMin_C: -55°C; Polarized: N; SizeAreaWB_mm2: 3; Value1: Unknown; U/M: EA; Value: 0.1uF; TaMax_C: 125°C; SizeZ_mm: 0.6; SizeX_mm: 1; SizeY_mm: 0.5; Cap_Case: 0402; CompType: Capacitor; AEC Qualified: Y; Cap_F: 100nF; AEC Category: Q200
C46 C49-C52 = CMP-0007977-2: CAP, CERM, 2.2 uF, 50 V, +/- 10%, X7R, AEC-Q200 Grade 1, 0805; Manufacturer: TDK; PartNumber: CGA4J3X7R1H225K125AB; TaMin_C: -55°C; ESR_ohm: 3.288m; Polarized: N; SizeAreaWB_mm2: 6.75; Value1: 0.003288 ohm; U/M: EA; Value: 2.2uF; TaMax_C: 125°C; SizeZ_mm: 1.45; SizeX_mm: 2; SizeY_mm: 1.25; Cap_Case: 0805; SizeArea_mm2: 2.5; CompType: Capacitor; AEC Qualified: Y; IRMS_A: 3.60029A; AEC Grade: 1; AEC Category: Q200
C47 C48 = CMP-0006328-2: CAP, CERM, 0.022 uF, 50 V, +/- 10%, X7R, AEC-Q200 Grade 1, 0402; Manufacturer: TDK; PartNumber: CGA2B3X7R1H223K050BB; TaMin_C: -55°C; ESR_ohm: 0.141987; Polarized: N; SizeAreaWB_mm2: 3; Value1: 0.141987 ohm; U/M: EA; TaMax_C: 125°C; SizeZ_mm: 0.6; SizeX_mm: 1; SizeY_mm: 0.5; Cap_Case: 0402; CompType: Capacitor; AEC Qualified: Y; Cap_F: 22nF; IRMS_A: 451.393mA; AEC Category: Q200
C101 = CMP-0085950-1: as C3 on sheet PMP23117_Schematic
FB2 = CMP-0093223-1: Chip Ferrite Bead Array, 1206, 50Ω @ 100MHz, 0.0016Ω, 25%, 12A; Manufacturer: Murata; AEC Grade: Grade 1; DCR_ohm: 1.6m; AEC Qualified: Yes; SizeZ_mm: 1.3mm; Import Ts: 1521846834; Ciiva Ids: 2806620
J6 = CMP-0054828-1: as J1 on sheet PMP23117_Schematic
L5 = CMP-0088899-2: Inductor, Shielded, Composite, 1.0H, 16.9 A, 0.0084 ohm, AEC-Q200 Grade 1; PartNumber: XEL5030-102MEB; Manufacturer: Coilcraft; Ind_H: 1µH; DCR_ohm: 8.4m; Test Frequency: 1MHz; TaMin_C: -40°C; SizeZ_mm: 3.1mm; Shrouded: true; AEC Grade: Grade 1; Irms: 15.4A; AEC Qualified: Yes; Standoff Height: 0.18mm; Tolerance_%: 20%; Self Resonant Frequency: 51MHz; TaMax_C: +125°C; Isat: 16.9A

## Sheet PMP23117_Hardware.SchDoc
size 431 x 279 mm; Date: Not shown in title block; ApprovedBy: Not shown in title block; CheckedBy: Not shown in title block; Author: Not shown in title block; CompanyName: Not shown in title block; Engineer: Not shown in title block; Organization: Not shown in title block; Address1: Not shown in title block; Address2: Not shown in title block; Address3: Not shown in title block; Address4: Not shown in title block; DocumentNumber: 3; Revision: Use project parameter SCH_Rev; SheetNumber: 3; SheetTotal: 3; PageSetup: Record=PageOptions¦CenterHorizontal=True¦CenterVertical=True¦PrintScale=1.00¦XCorrection=1.00¦YCorrection=1.00¦PrintKind=0¦BorderSize=5000000¦LeftOffset=0¦BottomOffset=0¦Orientation=2¦PaperLength=1000¦PaperWidth=1000¦Scale=100¦PaperSource=15¦PrintQuality=600¦MediaType=1¦DitherType=10¦PaperKind=Letter¦PrintScaleMode=1
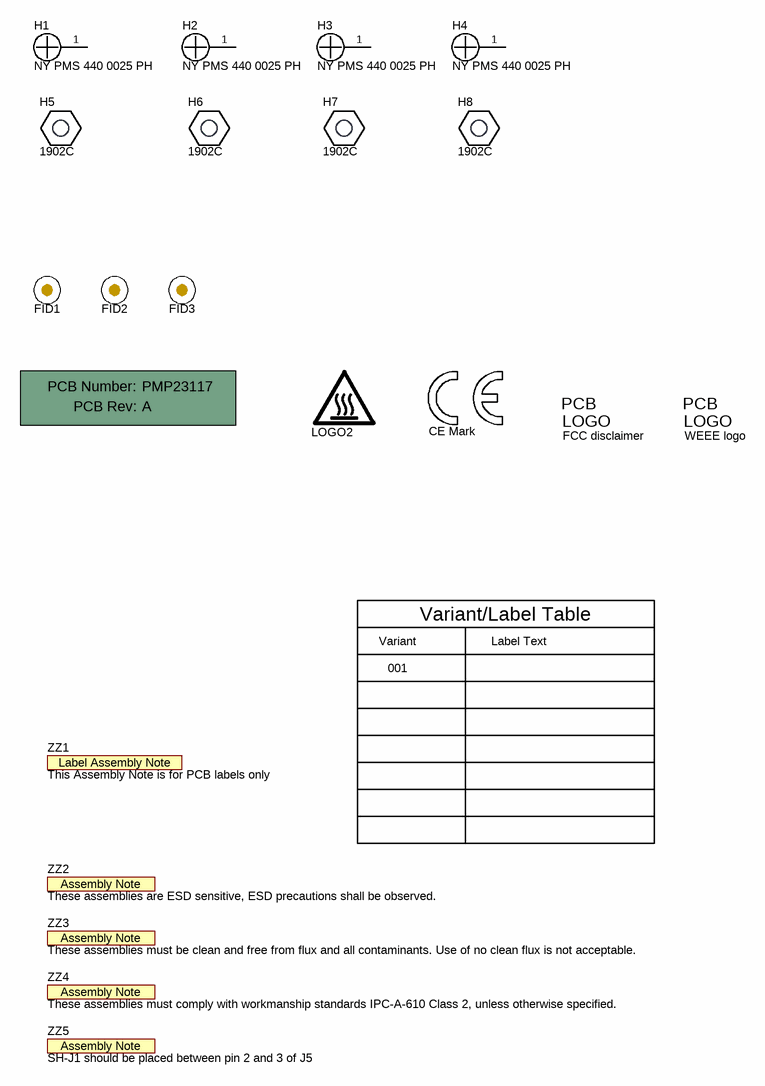
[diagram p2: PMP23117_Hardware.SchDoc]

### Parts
!PCB1  Printed Circuit Board  (value not drawn)  (mechanical)
FID1  Fiducial  [Fiducial10-20]  (value not drawn)
FID2  Fiducial  [Fiducial10-20]  (value not drawn)
FID3  Fiducial  [Fiducial10-20]  (value not drawn)
H1  NY PMS 440 0025 PH  [NY PMS 440 0025 PH]
H2  NY PMS 440 0025 PH  [NY PMS 440 0025 PH]
H3  NY PMS 440 0025 PH  [NY PMS 440 0025 PH]
H4  NY PMS 440 0025 PH  [NY PMS 440 0025 PH]
H5  1902C  [Keystone_1902C]
H6  1902C  [Keystone_1902C]
H7  1902C  [Keystone_1902C]
H8  1902C  [Keystone_1902C]
Logo1  CE Mark  [CE_Mark_5mm]  (no BOM)
LOGO2  CAUTION HOT SURFACE  [IEC_HotSurface_Small]  (value not drawn)  (no BOM)
Logo3  FCC disclaimer  [FCC_disclaimer]  (no BOM)
Logo4  WEEE logo  [WEEE_Minimum]  (no BOM)
ZZ1  This Assembly Note is for PCB labels only  [AssemblyNoteLabel]  (no BOM)
ZZ2  These assemblies are ESD sensitive, ESD precautions shall be observed.  [AssemblyNote]  (no BOM)
ZZ3  These assemblies must be clean and free from flux and all contaminants. Use of no clean flux is not acceptable.  [AssemblyNote]  (no BOM)
ZZ4  These assemblies must comply with workmanship standards IPC-A-610 Class 2, unless otherwise specified.  [AssemblyNote]  (no BOM)
ZZ5  SH-J1 should be placed between pin 2 and 3 of J5  [AssemblyNote]  (no BOM)

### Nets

Not connected (* = marked no-connect by the designer): H1 1; H2 1; H3 1; H4 1

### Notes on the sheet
- Variant
- Variant/Label Table
- Label Text
- 001

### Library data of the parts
!PCB1 = CMP-0003618-2: Manufacturer: Any; PartNumber: PMP23117
FID1-FID3 = CMP-0077181-1: Fiducial mark.  There is nothing to buy or mount.
H1-H4 = CMP-0003617-1: Machine Screw, Round, #4-40 x 1/4, Nylon, Philips panhead; Manufacturer: B&F Fastener Supply; CompType: Hardware
H5-H8 = CMP-0003610-1: Standoff, Hex, 0.5"L #4-40 Nylon; Manufacturer: Keystone; CompType: Hardware
Logo1 = CMP-0074844-1: SymbolCreator: a0412235
LOGO2 = CMP-0074837-1: IEC 61010-1 Hot Surface Warning; SymbolCreator: a0412235
Logo3 = CMP-0074847-1: FCC_disclaimer; Library Reference: Logo
Logo4 = CMP-0074769-1
ZZ1 = CMP-0003616-3
ZZ2 = CMP-0077236-1
ZZ3 = CMP-0077237-1
ZZ4 = CMP-0077238-1
ZZ5 = CMP-0077238-1: These assemblies must comply with workmanship standards IPC-A-610 Class 2, unless otherwise specified.

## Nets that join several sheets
GND: PMP23117_Schematic (67 pins), PMP23117_EMI_Filter (12 pins)
VIN: PMP23117_Schematic (20 pins), PMP23117_EMI_Filter (6 pins)

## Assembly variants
001: not fitted C10 C11 C12 C16 C20 C24 C32 C33 C36 C40 FID1 FID2 FID3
